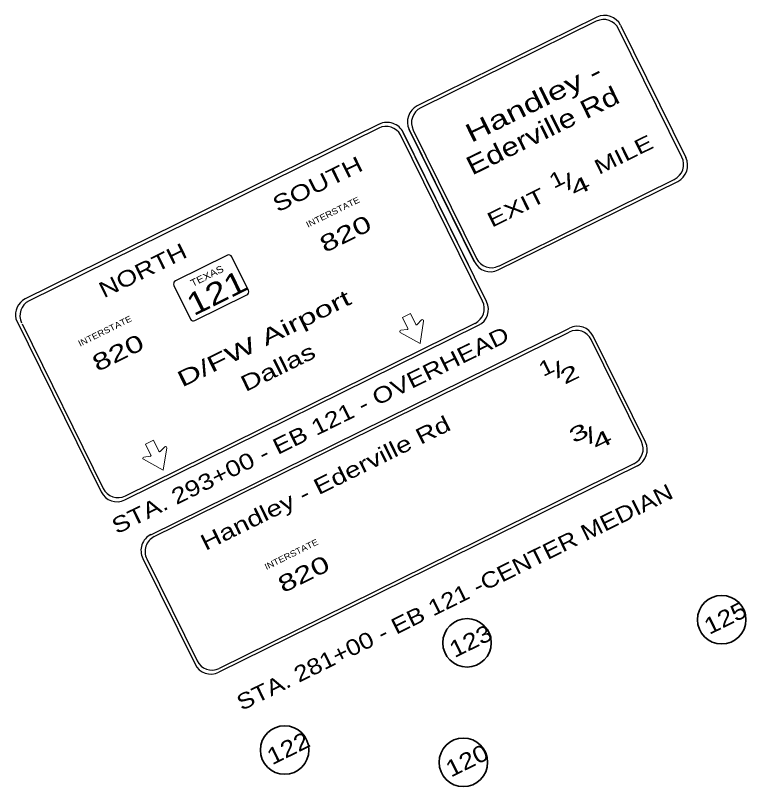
# Model space of a CAD drawing. Extents: x 2356431 to 2371438, y 6972864 to 6982525.
# Drawn here: x 2357741 to 2358362, y 6976001 to 6976656 of the extents above; entities that cross this region are included whole.
import ezdxf
from ezdxf.enums import TextEntityAlignment as Align

# ---------------------------------------------------------------- set-up
doc = ezdxf.new("R2010")
doc.units = 0
doc.header["$LTSCALE"] = 5.6
for name, color, linetype, lineweight in [('17', 7, 'Continuous', 35), ('48', 7, 'Continuous', 25), ('53', 7, 'Continuous', 13)]:
    doc.layers.add(name, color=color, linetype=linetype, lineweight=lineweight)

msp = doc.modelspace()

# ---------------------------------------------------------------- linework, layer by layer
at = {"layer": '17'}
for centre in [(2358340.929, 6976143.085), (2358124.729, 6976123.474), (2357969.87, 6976032.506), (2358121.632, 6976022.067)]:
    msp.add_circle(centre, 20.576, dxfattribs=at)
at = {"layer": '48'}
for p, q in [((2358234.928, 6976654.345), (2358082.489, 6976579.141)), ((2358234.477, 6976650.983), (2358085.418, 6976577.45)), ((2358255.073, 6976647.517), (2358310.447, 6976535.267)), ((2358307.078, 6976535.695), (2358253.368, 6976644.566)), ((2358050.257, 6976563.614), (2357749.658, 6976415.325)), ((2358049.829, 6976560.274), (2357752.925, 6976413.796)), ((2358137.923, 6976413.436), (2358068.322, 6976554.522)), ((2358075.64, 6976558.995), (2358131.014, 6976446.746)), ((2358079.017, 6976558.552), (2358132.727, 6976449.681)), ((2358151.18, 6976439.909), (2358303.597, 6976515.099)), ((2358151.616, 6976443.257), (2358300.676, 6976516.797)), ((2357921.25, 6976452.389), (2357877.096, 6976430.608)), ((2357939.14, 6976422.478), (2357925.015, 6976451.117)), ((2357875.815, 6976426.843), (2357889.947, 6976398.212)), ((2357893.714, 6976396.93), (2357937.861, 6976418.71)), ((2357741.709, 6976398.365), (2357814.121, 6976251.599)), ((2357746.892, 6976394.211), (2357815.803, 6976254.52)), ((2357834.207, 6976244.786), (2358134.466, 6976392.908)), ((2357834.641, 6976248.128), (2358131.546, 6976394.606)), ((2357856.279, 6976215.255), (2358211.749, 6976390.555)), ((2357859.199, 6976213.58), (2358211.283, 6976387.245)), ((2358276.16, 6976293.872), (2358231.819, 6976383.765)), ((2358272.812, 6976294.308), (2358230.129, 6976380.837)), ((2358269.334, 6976273.793), (2357913.871, 6976098.479)), ((2358266.412, 6976275.476), (2357914.314, 6976101.827)), ((2357849.459, 6976195.177), (2357893.8, 6976105.29)), ((2357852.814, 6976194.741), (2357895.491, 6976108.219))]:
    msp.add_line(p, q, dxfattribs=at)
for points in [[(2358141.286, 6976413.001), (2358070.489, 6976556.499), (2358125.666, 6976444.658)], [(2358130.808, 6976447.152), (2358075.64, 6976558.995), (2358130.816, 6976447.153)]]:
    msp.add_lwpolyline(points, dxfattribs=at)
for centre, radius, start, end in [((2358240.726, 6976638.333), 14.108, 26.25867, 116.25867), ((2358241.581, 6976640.852), 15.049, 26.25867, 116.25867), ((2358089.145, 6976565.65), 15.049, 116.25867, 206.25867), ((2358091.664, 6976564.796), 14.108, 116.25867, 206.25867), ((2358056.049, 6976547.656), 14.063, 29.21774, 116.25867), ((2358056.895, 6976550.164), 15.001, 24.97747, 116.25867), ((2358294.439, 6976529.456), 14.108, 296.25867, 26.25867), ((2358296.958, 6976528.601), 15.049, 296.25867, 26.25867), ((2357922.493, 6976449.875), 2.813, 26.25867, 116.25867), ((2358145.376, 6976455.919), 14.108, 206.25867, 296.25867), ((2358144.522, 6976453.399), 15.049, 206.25867, 296.25867), ((2357878.335, 6976428.09), 2.813, 116.25867, 206.25867), ((2357936.621, 6976421.237), 2.813, 296.25867, 26.25867), ((2357756.299, 6976401.868), 15.001, 116.25867, 193.48473), ((2357759.147, 6976401.182), 14.063, 116.25867, 206.25867), ((2358125.317, 6976407.213), 14.063, 296.25867, 26.25867), ((2358127.828, 6976406.361), 15.001, 296.25867, 26.25867), ((2357892.463, 6976399.453), 2.813, 206.25867, 296.25867), ((2358218.372, 6976377.123), 15.001, 26.25417, 116.25417), ((2358217.519, 6976374.612), 14.063, 26.25417, 116.25417), ((2358260.194, 6976288.087), 14.063, 296.25417, 26.25417), ((2358262.705, 6976287.235), 15.001, 296.25417, 26.25417), ((2357828.421, 6976260.742), 14.063, 206.25867, 296.25867), ((2357827.569, 6976258.23), 15.001, 206.25867, 296.25867), ((2357862.91, 6976201.814), 15.001, 116.25359, 206.25359), ((2357865.421, 6976200.961), 14.063, 116.25359, 206.25359), ((2357907.243, 6976111.925), 15.001, 206.25359, 296.25359), ((2357908.095, 6976114.436), 14.063, 206.25359, 296.25359)]:
    msp.add_arc(centre, radius, start, end, dxfattribs=at)
at = {"layer": '53'}
for p, q in [((2358086.139, 6976397.47), (2358082.313, 6976393.477)), ((2358068.043, 6976386.82), (2358068.069, 6976386.803)), ((2358073.902, 6976389.326), (2358068.39, 6976388.721)), ((2357868.049, 6976289.892), (2357864.222, 6976285.892)), ((2357866.804, 6976270.037), (2357869.771, 6976288.98)), ((2357849.979, 6976279.22), (2357866.804, 6976270.037)), ((2357855.821, 6976281.749), (2357850.309, 6976281.136))]:
    msp.add_line(p, q, dxfattribs=at)
for points in [[(2358081.205, 6976393.641), (2358076.607, 6976402.956), (2358073.221, 6976401.283), (2358069.834, 6976399.619), (2358074.431, 6976390.295)], [(2358068.069, 6976386.803), (2358084.895, 6976377.622), (2358087.861, 6976396.565)], [(2357863.114, 6976286.055), (2357858.524, 6976295.378), (2357855.129, 6976293.698), (2357851.751, 6976292.034), (2357856.342, 6976282.718)]]:
    msp.add_lwpolyline(points, dxfattribs=at)
for centre, radius, start, end in [((2358086.864, 6976396.757), 1.012, 350.99716, 136.3783), ((2358073.836, 6976389.985), 0.675, 276.27556, 26.25867), ((2358081.827, 6976393.927), 0.675, 206.25867, 316.24177), ((2358068.526, 6976387.71), 1.012, 96.13904, 241.52017), ((2357863.74, 6976286.345), 0.675, 206.25867, 316.24177), ((2357868.777, 6976289.175), 1.012, 350.99716, 136.3783), ((2357850.439, 6976280.128), 1.012, 96.13904, 241.52017), ((2357855.749, 6976282.403), 0.675, 276.27556, 26.25867)]:
    msp.add_arc(centre, radius, start, end, dxfattribs=at)

# ---------------------------------------------------------------- texts
at = {"layer": '17', "width": 1.2}
for s, p in [('125', (2358347.125, 6976138.336)), ('123', (2358130.924, 6976118.725)), ('122', (2357976.066, 6976027.757)), ('120', (2358127.827, 6976017.318))]:
    msp.add_text(s, height=14, rotation=26.268, dxfattribs=at).set_placement(p, align=Align.CENTER)
at = {"layer": '48'}
for s, height, rotation, width, p in [('Handley -', 15.68, 26.259, 1.4, (2358184.564, 6976575.412)), ('Ederville Rd', 15.68, 26.259, 1.25, (2358192.358, 6976551.175)), ('MILE', 12.54, 26.259, 1.35, (2358260.393, 6976532.198)), ('SOUTH', 13.5, 26.259, 1.3, (2358000.796, 6976506.69)), ('1', 12.54, 26.259, 1.3, (2358203.724, 6976511.351)), ('/', 12.54, 26.259, 1.7, (2358213.931, 6976509.282)), ('4', 12.54, 26.259, 1.75, (2358223.419, 6976505.525)), ('EXIT', 12.54, 26.259, 1.4, (2358169.176, 6976487.199)), ('NORTH', 13.5, 26.259, 1.25, (2357852.374, 6976433.478)), ('D/FW Airport', 13.49, 26.259, 1.55, (2357955.293, 6976375.774)), ('STA. 293+00 - EB 121 - OVERHEAD', 13.5, 26.253, 1.25, (2357994.67, 6976297.924)), ('Dallas', 13.5, 26.259, 1.35, (2357967.135, 6976351.176)), ('1', 12.54, 26.254, 1.3, (2358194.773, 6976351.648)), ('/', 12.54, 26.254, 1.7, (2358204.996, 6976349.577)), ('2', 12.54, 26.254, 1.65, (2358214.478, 6976345.831)), ('Handley - Ederville Rd', 13.5, 26.253, 1.3, (2358007.445, 6976253.017)), ('3', 12.54, 26.254, 1.7, (2358222.225, 6976296.02)), ('/', 12.54, 26.254, 1.7, (2358232.446, 6976293.949)), ('4', 12.54, 26.254, 1.75, (2358241.926, 6976290.202)), ('STA. 281+00 - EB 121 -CENTER MEDIAN', 13.5, 26.253, 1.2, (2358117.202, 6976156.237))]:
    msp.add_text(s, height=height, rotation=rotation, dxfattribs=dict(at, width=width)).set_placement(p, align=Align.CENTER)
for s, height, rotation, width, p in [('INTERSTATE', 5.197, 26.258, 1.15, (2357989.639, 6976475.658)), ('TEXAS', 6, 26.259, 1.15, (2357891.725, 6976425.45)), ('121', 18.75, 26.259, 1.25, (2357892.688, 6976400.558)), ('INTERSTATE', 5.197, 26.258, 1.15, (2357796.149, 6976374.746)), ('820', 14.18, 26.258, 1.45, (2357810.937, 6976353.202)), ('INTERSTATE', 5.195, 26.259, 1.15, (2357954.409, 6976185.281)), ('820', 14.17, 26.259, 1.45, (2357968.61, 6976165.426))]:
    msp.add_text(s, height=height, rotation=rotation, dxfattribs=dict(at, width=width)).set_placement(p)
at = {"layer": '53', "width": 1.45}
msp.add_text('820', height=14.18, rotation=26.258, dxfattribs=at).set_placement((2358004.084, 6976454.152))

doc.saveas('drawing.dxf')
